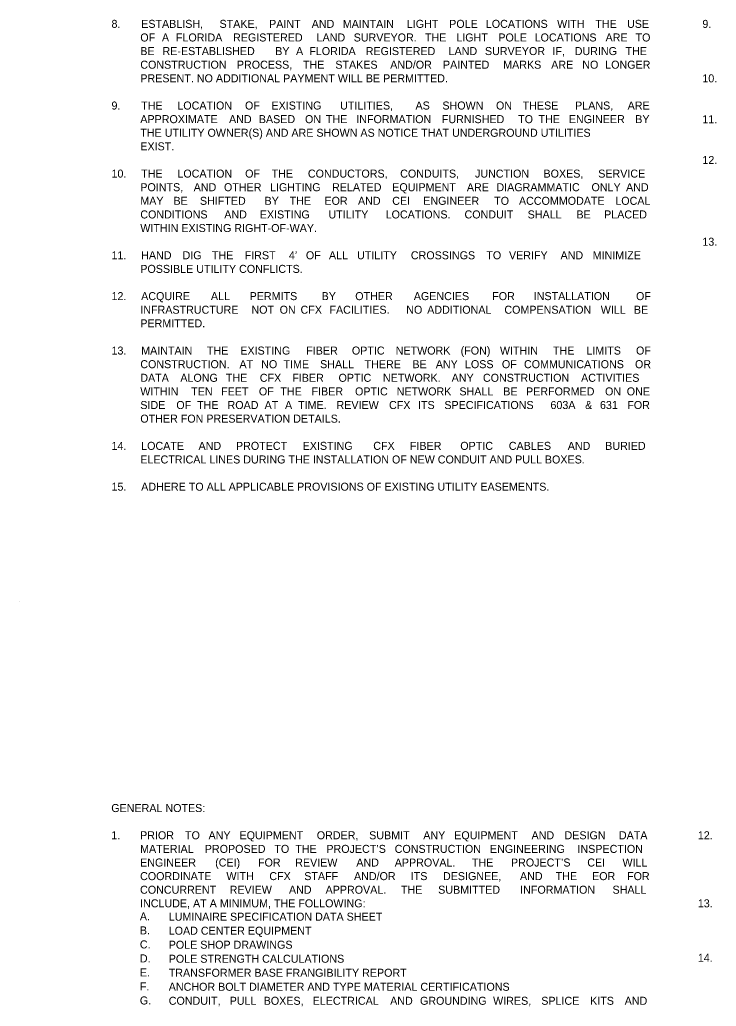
# Model space of a CAD drawing. Extents: x -55 to 2471539, y -90 to 3608906.
# Drawn here: x -54 to 555, y 779 to 1641 of the extents above; entities that cross this region are included whole.
import ezdxf

# ---------------------------------------------------------------- set-up
doc = ezdxf.new("R2010")
doc.units = 0
doc.layers.add('TextMinor', color=7, linetype='Continuous')
doc.layers.add('XSCell', color=7, linetype='Continuous')

msp = doc.modelspace()

# ---------------------------------------------------------------- linework, layer by layer
at = {"layer": 'TextMinor'}
msp.add_line((-54.3, 1133.16), (-54.3, 1133.16), dxfattribs=at)

# ---------------------------------------------------------------- texts
at = {"layer": 'XSCell'}
for s, p in [('8.', (25.93, 1634.2)), ('ESTABLISH, ', (51.88, 1634.2)), ('STAKE, ', (120.37, 1634.2)), ('PAINT ', (163.7, 1634.2)), ('AND ', (200.95, 1634.2)), ('MAINTAIN ', (228.11, 1634.2)), ('LIGHT ', (284.09, 1634.2)), ('POLE ', (321.15, 1634.2)), ('LOCATIONS ', (353.19, 1634.2)), ('WITH ', (415.49, 1634.2)), ('THE ', (448.94, 1634.2)), ('USE ', (476.64, 1634.2)), ('9.', (542.46, 1634.16)), ('OF ', (51.12, 1622.3)), ('A ', (70.02, 1622.3)), ('FLORIDA ', (82.24, 1622.3)), ('REGISTERED ', (132.19, 1622.3)), ('LAND ', (205.23, 1622.3)), ('SURVEYOR. ', (237.62, 1622.3)), ('THE ', (299.99, 1622.3)), ('LIGHT ', (327.38, 1622.3)), ('POLE ', (364.11, 1622.3)), ('LOCATIONS ', (395.84, 1622.3)), ('ARE ', (457.83, 1622.3)), ('TO ', (484.06, 1622.3)), ('BE ', (51.12, 1610.4)), ('RE-ESTABLISHED ', (70.53, 1610.4)), ('BY ', (169.03, 1610.4)), ('A ', (187.23, 1610.4)), ('FLORIDA ', (198.84, 1610.4)), ('REGISTERED ', (248.18, 1610.4)), ('LAND ', (320.61, 1610.4)), ('SURVEYOR ', (352.39, 1610.4)), ('IF, ', (411.39, 1610.4)), ('DURING ', (430.89, 1610.4)), ('THE ', (475.23, 1610.4)), ('CONSTRUCTION ', (51.12, 1598.5)), ('PROCESS, ', (135.53, 1598.5)), ('THE ', (193.29, 1598.5)), ('STAKES ', (221.6, 1598.5)), ('AND/OR ', (269.57, 1598.5)), ('PAINTED ', (315.68, 1598.5)), ('MARKS ', (368.35, 1598.5)), ('ARE ', (410.33, 1598.5)), ('NO ', (437.49, 1598.5)), ('LONGER ', (457.53, 1598.5)), ('PRESENT. NO ADDITIONAL PAYMENT WILL BE PERMITTED.', (51.12, 1586.6)), ('10.', (542.46, 1586.56)), ('9.', (25.93, 1562.8)), ('THE ', (51.88, 1562.8)), ('LOCATION ', (83.48, 1562.8)), ('OF ', (142.62, 1562.8)), ('EXISTING ', (165.74, 1562.8)), ('UTILITIES, ', (225.78, 1562.8)), ('AS ', (291.68, 1562.8)), ('SHOWN ', (315.2, 1562.8)), ('ON ', (362.04, 1562.8)), ('THESE ', (385.38, 1562.8)), ('PLANS, ', (431.2, 1562.8)), ('ARE ', (477.14, 1562.8)), ('APPROXIMATE ', (51.12, 1550.9)), ('AND ', (128.7, 1550.9)), ('BASED ', (154.72, 1550.9)), ('ON ', (195.09, 1550.9)), ('THE ', (213.38, 1550.9)), ('INFORMATION ', (239.94, 1550.9)), ('FURNISHED ', (314.71, 1550.9)), ('TO ', (381.43, 1550.9)), ('THE ', (399.16, 1550.9)), ('ENGINEER ', (425.72, 1550.9)), ('BY ', (483.8, 1550.9)), ('11.', (542.46, 1550.86)), ('THE UTILITY OWNER(S) AND ARE SHOWN AS NOTICE THAT UNDERGROUND UTILITIES ', (51.12, 1539)), ('EXIST.', (51.12, 1527.1)), ('12.', (542.46, 1515.16)), ('10.', (25.93, 1503.3)), ('THE ', (51.88, 1503.3)), ('LOCATION ', (83.55, 1503.3)), ('OF ', (142.75, 1503.3)), ('THE ', (165.94, 1503.3)), ('CONDUCTORS, ', (197.62, 1503.3)), ('CONDUITS, ', (278.3, 1503.3)), ('JUNCTION ', (343.7, 1503.3)), ('BOXES, ', (403.57, 1503.3)), ('SERVICE ', (451.42, 1503.3)), ('POINTS, ', (51.12, 1491.4)), ('AND ', (97.78, 1491.4)), ('OTHER ', (124.25, 1491.4)), ('LIGHTING ', (164.51, 1491.4)), ('RELATED ', (218.76, 1491.4)), ('EQUIPMENT ', (271.36, 1491.4)), ('ARE ', (336.58, 1491.4)), ('DIAGRAMMATIC ', (362.44, 1491.4)), ('ONLY ', (445.54, 1491.4)), ('AND ', (475.77, 1491.4)), ('MAY ', (51.12, 1479.5)), ('BE ', (80.1, 1479.5)), ('SHIFTED ', (103.22, 1479.5)), ('BY ', (159.71, 1479.5)), ('THE ', (181.63, 1479.5)), ('EOR ', (212.11, 1479.5)), ('AND ', (241.4, 1479.5)), ('CEI ', (271.34, 1479.5)), ('ENGINEER ', (298.47, 1479.5)), ('TO ', (360.47, 1479.5)), ('ACCOMMODATE ', (382.12, 1479.5)), ('LOCAL ', (466.36, 1479.5)), ('CONDITIONS ', (51.12, 1467.6)), ('EXISTING ', (155.55, 1467.6)), ('LOCATIONS. ', (265.58, 1467.6)), ('CONDUIT ', (334.53, 1467.6)), ('SHALL ', (389.71, 1467.6)), ('PLACED ', (456.59, 1467.6)), ('AND ', (124.51, 1467.6)), ('UTILITY ', (215.58, 1467.6)), ('BE ', (432.37, 1467.6)), ('WITHIN EXISTING RIGHT-OF-WAY.', (51.12, 1455.7)), ('13.', (542.46, 1443.76)), ('11.', (25.93, 1431.9)), ('HAND ', (51.88, 1431.9)), ('DIG ', (88.04, 1431.9)), ('THE ', (113.72, 1431.9)), ('FIRST ', (142.35, 1431.9)), ('4’ ', (180.98, 1431.9)), ('OF ', (195.88, 1431.9)), ('ALL ', (216.02, 1431.9)), ('UTILITY ', (240.58, 1431.9)), ('CROSSINGS ', (287.63, 1431.9)), ('TO ', (353.61, 1431.9)), ('VERIFY ', (373.41, 1431.9)), ('AND ', (418.48, 1431.9)), ('MINIMIZE ', (446.58, 1431.9)), ('POSSIBLE UTILITY CONFLICTS.', (51.12, 1420)), ('12.', (25.93, 1396.2)), ('ACQUIRE ', (51.88, 1396.2)), ('ALL ', (112.83, 1396.2)), ('PERMITS ', (146.69, 1396.2)), ('BY ', (209.63, 1396.2)), ('OTHER ', (239, 1396.2)), ('AGENCIES ', (290.18, 1396.2)), ('FOR ', (358.74, 1396.2)), ('INSTALLATION ', (395.06, 1396.2)), ('OF ', (484.48, 1396.2)), ('INFRASTRUCTURE ', (51.12, 1384.3)), ('NOT ', (148.26, 1384.3)), ('ON ', (172.92, 1384.3)), ('CFX ', (191.2, 1384.3)), ('FACILITIES. ', (216.47, 1384.3)), ('NO ', (283.62, 1384.3)), ('ADDITIONAL ', (301.9, 1384.3)), ('COMPENSATION ', (369.37, 1384.3)), ('WILL ', (453.64, 1384.3)), ('BE ', (482.6, 1384.3)), ('PERMITTED.', (51.12, 1372.4)), ('13.', (25.93, 1348.6)), ('MAINTAIN ', (51.88, 1348.6)), ('THE ', (109.34, 1348.6)), ('EXISTING ', (138.52, 1348.6)), ('FIBER ', (196.14, 1348.6)), ('OPTIC ', (236.08, 1348.6)), ('NETWORK ', (274.38, 1348.6)), ('(FON) ', (331.18, 1348.6)), ('WITHIN ', (365.51, 1348.6)), ('THE ', (411.91, 1348.6)), ('LIMITS ', (441.09, 1348.6)), ('OF ', (484.48, 1348.6)), ('CONSTRUCTION. ', (51.12, 1336.7)), ('AT ', (137.78, 1336.7)), ('NO ', (156.79, 1336.7)), ('TIME ', (176.31, 1336.7)), ('SHALL ', (208.3, 1336.7)), ('THERE ', (247.17, 1336.7)), ('BE ', (288.98, 1336.7)), ('ANY ', (309.41, 1336.7)), ('LOSS ', (334.92, 1336.7)), ('OF ', (367.21, 1336.7)), ('COMMUNICATIONS ', (386.52, 1336.7)), ('OR ', (483.56, 1336.7)), ('DATA ', (51.12, 1324.8)), ('ALONG ', (86.11, 1324.8)), ('THE ', (125.89, 1324.8)), ('CFX ', (155.57, 1324.8)), ('FIBER ', (183.98, 1324.8)), ('OPTIC ', (224.42, 1324.8)), ('NETWORK. ', (263.22, 1324.8)), ('ANY ', (323.28, 1324.8)), ('CONSTRUCTION ', (350.66, 1324.8)), ('ACTIVITIES ', (436.44, 1324.8)), ('WITHIN ', (51.12, 1312.9)), ('TEN ', (95.6, 1312.9)), ('FEET ', (121.73, 1312.9)), ('OF ', (154.77, 1312.9)), ('THE ', (173.54, 1312.9)), ('FIBER ', (200.8, 1312.9)), ('OPTIC ', (238.82, 1312.9)), ('NETWORK ', (275.2, 1312.9)), ('SHALL ', (330.08, 1312.9)), ('BE ', (368.42, 1312.9)), ('PERFORMED ', (388.31, 1312.9)), ('ON ', (457.38, 1312.9)), ('ONE ', (476.37, 1312.9)), ('SIDE ', (51.12, 1301)), ('OF ', (82.6, 1301)), ('THE ', (100.74, 1301)), ('ROAD ', (127.36, 1301)), ('AT ', (159.76, 1301)), ('A ', (177.6, 1301)), ('TIME. ', (189.06, 1301)), ('REVIEW ', (222.63, 1301)), ('CFX ', (268.54, 1301)), ('ITS ', (293.89, 1301)), ('SPECIFICATIONS ', (316.92, 1301)), ('603A ', (409.66, 1301)), ('& ', (439.98, 1301)), ('631 ', (452.94, 1301)), ('FOR ', (476.84, 1301)), ('OTHER FON PRESERVATION DETAILS.', (51.12, 1289.1)), ('14.', (25.93, 1265.3)), ('LOCATE ', (51.88, 1265.3)), ('AND ', (102, 1265.3)), ('PROTECT ', (134.75, 1265.3)), ('EXISTING ', (193.03, 1265.3)), ('CFX ', (254.76, 1265.3)), ('FIBER ', (286.78, 1265.3)), ('OPTIC ', (330.84, 1265.3)), ('CABLES ', (373.25, 1265.3)), ('AND ', (424.79, 1265.3)), ('BURIED ', (457.54, 1265.3)), ('ELECTRICAL LINES DURING THE INSTALLATION OF NEW CONDUIT AND PULL BOXES.', (51.12, 1253.4)), ('15.', (25.93, 1229.6)), ('ADHERE TO ALL APPLICABLE PROVISIONS OF EXISTING UTILITY EASEMENTS.', (51.88, 1229.6)), ('GENERAL NOTES:', (25.72, 948.68)), ('1.', (25.72, 924.88)), ('PRIOR ', (50.92, 924.88)), ('TO ', (90.22, 924.88)), ('ANY ', (110.76, 924.88)), ('EQUIPMENT ', (137.83, 924.88)), ('ORDER, ', (205.4, 924.88)), ('SUBMIT ', (251.19, 924.88)), ('ANY ', (298.48, 924.88)), ('EQUIPMENT ', (325.55, 924.88)), ('AND ', (393.12, 924.88)), ('DESIGN ', (421.95, 924.88)), ('DATA ', (469.51, 924.88)), ('12.', (538.51, 924.88)), ('MATERIAL ', (50.92, 912.98)), ('PROPOSED ', (107.5, 912.98)), ('TO ', (168.31, 912.98)), ('THE ', (186.62, 912.98)), ('PROJECT’S ', (213.77, 912.98)), ('CONSTRUCTION ', (273.5, 912.98)), ('ENGINEERING ', (356.75, 912.98)), ('INSPECTION ', (433.29, 912.98)), ('ENGINEER ', (50.92, 901.08)), ('(CEI) ', (116.56, 901.08)), ('FOR ', (154.03, 901.08)), ('REVIEW ', (186.54, 901.08)), ('AND ', (239.95, 901.08)), ('APPROVAL. ', (273.53, 901.08)), ('THE ', (341.01, 901.08)), ('PROJECT’S ', (375.14, 901.08)), ('CEI ', (441.85, 901.08)), ('WILL ', (472.62, 901.08)), ('COORDINATE ', (50.92, 889.18)), ('WITH ', (126.38, 889.18)), ('CFX ', (163.91, 889.18)), ('STAFF ', (194.42, 889.18)), ('AND/OR ', (237.93, 889.18)), ('ITS ', (287.52, 889.18)), ('DESIGNEE, ', (315.71, 889.18)), ('AND ', (383.02, 889.18)), ('THE ', (414.26, 889.18)), ('EOR ', (446.05, 889.18)), ('FOR ', (476.64, 889.18)), ('CONCURRENT ', (50.92, 877.28)), ('REVIEW ', (129.22, 877.28)), ('AND ', (181.06, 877.28)), ('APPROVAL. ', (213.07, 877.28)), ('THE ', (278.98, 877.28)), ('SUBMITTED ', (311.52, 877.28)), ('INFORMATION ', (383.19, 877.28)), ('SHALL ', (463.94, 877.28)), ('INCLUDE, AT A MINIMUM, THE FOLLOWING:', (50.92, 865.38)), ('13.', (538.51, 865.38)), ('A.', (50.72, 853.98)), ('LUMINAIRE SPECIFICATION DATA SHEET', (75.97, 853.71)), ('B.', (50.72, 841.73)), ('LOAD CENTER EQUIPMENT', (75.97, 841.46)), ('C.', (50.72, 829.48)), ('POLE SHOP DRAWINGS', (75.97, 829.21)), ('D.', (50.72, 817.23)), ('POLE STRENGTH CALCULATIONS', (75.97, 816.96)), ('14.', (538.51, 817.78)), ('E.', (50.72, 804.98)), ('TRANSFORMER BASE FRANGIBILITY REPORT', (75.97, 804.71)), ('F.', (50.72, 792.73)), ('ANCHOR BOLT DIAMETER AND TYPE MATERIAL CERTIFICATIONS', (75.97, 792.46)), ('G.', (50.72, 780.48)), ('CONDUIT, ', (75.97, 780.21)), ('PULL ', (129.25, 780.21)), ('BOXES, ', (158.98, 780.21)), ('ELECTRICAL ', (201.78, 780.21)), ('AND ', (269.51, 780.21)), ('GROUNDING ', (295.61, 780.21)), ('WIRES, ', (359.52, 780.21)), ('SPLICE ', (401.61, 780.21)), ('KITS ', (444.38, 780.21)), ('AND ', (474.57, 780.21))]:
    msp.add_text(s, height=7, dxfattribs=at).set_placement(p)

doc.saveas('drawing.dxf')
